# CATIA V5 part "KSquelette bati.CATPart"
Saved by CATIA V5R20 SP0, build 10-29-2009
Part number: K_Squelette bati
Bounding box of the stored display mesh (mm): x -50 to 50, y 125 to 160, z 190 to 570
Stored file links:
  C:\Users\thinkmotion1\Desktop\Khaled_IAO_Pack2\IAO_2010_1392_rragonneau\CATIA_1392_rragonneau\KSquelette bati.CATPart
  D:\Documents\Scolaire\MM2\IAO\Squelette\Product1.CATProduct
  C:\Users\thinkmotion1\Desktop\Khaled_IAO_Pack2\IAO_2010_1392_rragonneau\CATIA_1392_rragonneau\KSquelette de base.CATPart
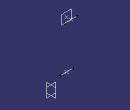
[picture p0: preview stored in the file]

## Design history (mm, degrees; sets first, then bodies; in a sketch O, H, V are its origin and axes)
Set1
  Line1: type Normal, RefPoint Point1, RefSkin Plane3, Start -50, End 50
  Line2: type Normal, RefPoint Point2, RefSkin Plane1, Start -50, End 50
  Plane1: stored without definition
  Plane2: type OffsetPt, RefPlane Plane4, RefPoint Point3
Set2
  Plane3: linked copy from another document
  Point1: linked copy from another document
  Point2: linked copy from another document
  Plane4: linked copy from another document
  Point3: linked copy from another document
Body1 (main body)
